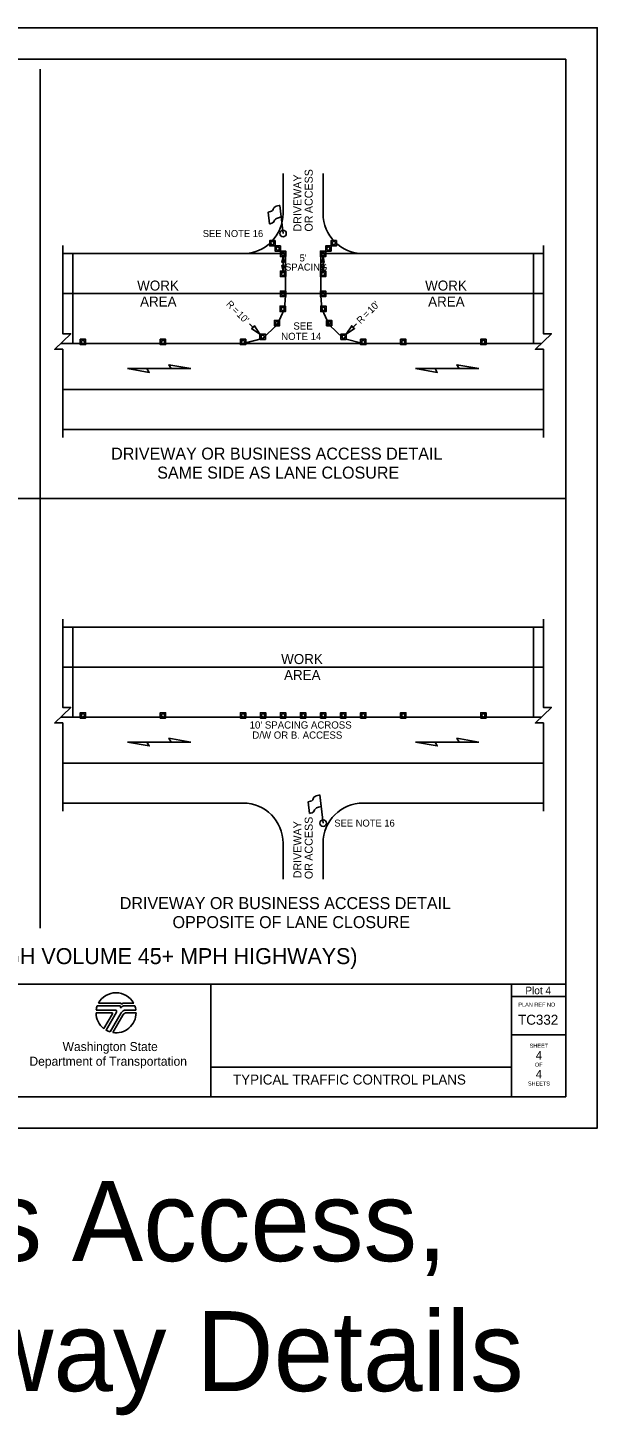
# Model space of a CAD drawing. Extents: x 99999.1 to 100095.7, y 99995 to 100010.7.
# Drawn here: x 100070.38 to 100076.06, y 99996.82 to 100010.69 of the extents above; entities that cross this region are included whole.
import ezdxf

# ---------------------------------------------------------------- set-up
doc = ezdxf.new("R2010")
doc.units = 0
for name, color, linetype in [('RD_ED_DrivewayEdge', 7, 'Continuous'), ('RD_ED_ShoulderPavedEdge', 7, 'Continuous'), ('RD_MK_LineEdgeWhite', 7, 'Continuous'), ('RD_MK_LineSkipCenter', 7, 'Continuous'), ('SH_DE_DetailHeading1Text', 7, 'Continuous'), ('SH_DE_DetailHeading2Text', 7, 'Continuous'), ('SH_GI_PlotLimits', 7, 'Continuous'), ('SH_GI_SheetBorder', 7, 'Continuous'), ('SH_GI_SheetLocationText', 7, 'Continuous'), ('SH_GI_SheetTextInCells', 7, 'Continuous'), ('SH_GI_TitleBlockText', 7, 'Continuous'), ('SH_GI_WSDOTLogo', 7, 'Continuous'), ('TR_WZ_FlaggingStation', 7, 'Continuous'), ('TR_WZ_TrafficCone', 7, 'Continuous'), ('TR_WZ_WorkAreaLabel', 7, 'Continuous'), ('TR_WZ_WorkZoneDetails', 7, 'Continuous'), ('TR_WZ_WorkZoneTextCurrent', 7, 'Continuous')]:
    doc.layers.add(name, color=color, linetype=linetype)

msp = doc.modelspace()

# ---------------------------------------------------------------- linework, layer by layer
at = {"layer": 'RD_ED_DrivewayEdge'}
for p, q in [((100072.925, 100008.83), (100072.925, 100009.23)), ((100073.325, 100008.83), (100073.325, 100009.23)), ((100072.925, 100002.536), (100072.925, 100002.176)), ((100073.325, 100002.536), (100073.325, 100002.176))]:
    msp.add_line(p, q, dxfattribs=at)
for centre, start, end in [((100072.525, 100008.83), 270, 0), ((100073.725, 100008.83), 180, 270), ((100072.525, 100002.536), 0, 90), ((100073.725, 100002.536), 90, 180)]:
    msp.add_arc(centre, 0.4, start, end, dxfattribs=at)
at = {"layer": 'RD_ED_ShoulderPavedEdge'}
for p, q in [((100070.725, 100008.43), (100072.525, 100008.43)), ((100073.725, 100008.43), (100075.525, 100008.43)), ((100070.725, 100006.67), (100075.525, 100006.67)), ((100070.725, 100004.696), (100075.525, 100004.696)), ((100070.725, 100002.936), (100072.525, 100002.936)), ((100073.725, 100002.936), (100075.525, 100002.936))]:
    msp.add_line(p, q, dxfattribs=at)
at = {"layer": 'RD_MK_LineEdgeWhite'}
for p, q in [((100070.725, 100008.03), (100075.525, 100008.03)), ((100070.725, 100007.07), (100075.525, 100007.07)), ((100070.725, 100004.296), (100075.525, 100004.296)), ((100070.725, 100003.336), (100075.525, 100003.336))]:
    msp.add_line(p, q, dxfattribs=at)
at = {"layer": 'RD_MK_LineSkipCenter'}
for points in [[(100075.504, 100007.53), (100070.704, 100007.53)], [(100075.504, 100003.796), (100070.704, 100003.796)]]:
    msp.add_lwpolyline(points, dxfattribs=at)
at = {"layer": 'SH_GI_PlotLimits'}
msp.add_lwpolyline([(100059.062, 99999.687), (100076.062, 99999.687), (100076.062, 100010.687), (100059.062, 100010.687)], close=True, dxfattribs=at)
at = {"layer": 'SH_GI_SheetBorder'}
for p, q in [((100060, 100010.375), (100075.75, 100010.375)), ((100075.75, 100010.375), (100075.75, 100000)), ((100060, 100001.126), (100075.75, 100001.126)), ((100072.205, 100001.126), (100072.205, 100000)), ((100075.208, 100001.126), (100075.208, 100000)), ((100075.208, 100001.001), (100075.75, 100001.001)), ((100075.208, 100000.618), (100075.75, 100000.618)), ((100072.205, 100000.295), (100075.208, 100000.295)), ((100060, 100000), (100075.75, 100000))]:
    msp.add_line(p, q, dxfattribs=at)
at = {"layer": 'SH_GI_WSDOTLogo'}
for p, q in [((100071.059, 100000.866), (100071.25, 100000.866)), ((100071.289, 100000.909), (100071.07, 100000.909)), ((100071.303, 100000.935), (100071.081, 100000.935)), ((100071.433, 100000.935), (100071.335, 100000.935)), ((100071.445, 100000.909), (100071.343, 100000.909)), ((100071.343, 100000.909), (100071.343, 100000.909)), ((100071.356, 100000.866), (100071.456, 100000.866)), ((100071.057, 100000.84), (100071.215, 100000.84)), ((100071.222, 100000.828), (100071.136, 100000.681)), ((100071.261, 100000.846), (100071.157, 100000.667)), ((100071.199, 100000.649), (100071.309, 100000.839)), ((100071.224, 100000.643), (100071.324, 100000.816)), ((100071.365, 100000.839), (100071.457, 100000.839))]:
    msp.add_line(p, q, dxfattribs=at)
for centre, radius, start, end in [((100071.257, 100000.84), 0.2, 28.4787, 151.532), ((100071.257, 100000.84), 0.2, 159.696, 172.5057), ((100071.25, 100000.853), 0.0131, 329.7683, 90), ((100071.289, 100000.895), 0.0148, 327.8418, 89.9985), ((100071.343, 100000.861), 0.0484, 89.9953, 147.8238), ((100071.303, 100000.926), 0.00903, 329.8742, 90.0033), ((100071.356, 100000.812), 0.0542, 90, 149.9974), ((100071.335, 100000.907), 0.0287, 90.0072, 148.1676), ((100071.257, 100000.84), 0.2, 7.4943, 20.2941), ((100071.257, 100000.84), 0.2, 179.9986, 232.8433), ((100071.215, 100000.832), 0.0082, 329.7436, 90), ((100071.257, 100000.84), 0.2, 260.5455, 359.8086), ((100071.365, 100000.792), 0.0476, 90, 150.0543), ((100071.257, 100000.84), 0.2, 239.7929, 253.0448)]:
    msp.add_arc(centre, radius, start, end, dxfattribs=at)
at = {"layer": 'TR_WZ_FlaggingStation'}
for p, q in [((100072.906, 100008.797), (100072.893, 100008.912)), ((100072.925, 100008.63), (100072.893, 100008.911)), ((100072.775, 100008.844), (100072.788, 100008.727)), ((100072.906, 100008.797), (100072.906, 100008.797)), ((100073.175, 100002.949), (100073.188, 100002.832)), ((100073.325, 100002.736), (100073.293, 100003.017)), ((100073.306, 100002.903), (100073.293, 100003.017)), ((100073.306, 100002.903), (100073.306, 100002.903))]:
    msp.add_line(p, q, dxfattribs=at)
for points in [[(100072.893, 100008.912), (100072.887, 100008.91), (100072.869, 100008.907), (100072.856, 100008.903), (100072.846, 100008.897), (100072.837, 100008.892), (100072.832, 100008.885), (100072.827, 100008.877), (100072.827, 100008.871), (100072.821, 100008.862), (100072.811, 100008.854), (100072.798, 100008.849), (100072.775, 100008.844)], [(100072.788, 100008.727), (100072.796, 100008.728), (100072.814, 100008.733), (100072.83, 100008.743), (100072.836, 100008.754), (100072.84, 100008.764), (100072.849, 100008.775), (100072.86, 100008.781), (100072.878, 100008.788), (100072.906, 100008.797)], [(100073.293, 100003.017), (100073.287, 100003.016), (100073.269, 100003.012), (100073.256, 100003.008), (100073.246, 100003.002), (100073.237, 100002.997), (100073.232, 100002.991), (100073.227, 100002.983), (100073.227, 100002.977), (100073.221, 100002.967), (100073.211, 100002.96), (100073.198, 100002.955), (100073.175, 100002.949)], [(100073.188, 100002.832), (100073.196, 100002.834), (100073.214, 100002.838), (100073.23, 100002.849), (100073.236, 100002.859), (100073.24, 100002.87), (100073.249, 100002.88), (100073.26, 100002.887), (100073.278, 100002.894), (100073.306, 100002.903)]]:
    msp.add_lwpolyline(points, dxfattribs=at)
for centre in [(100072.925, 100008.63), (100073.325, 100002.736)]:
    msp.add_circle(centre, 0.0325, dxfattribs=at)
at = {"layer": 'TR_WZ_TrafficCone'}
for points in [[(100072.845, 100008.56), (100072.845, 100008.507), (100072.792, 100008.507), (100072.792, 100008.56), (100072.845, 100008.56)], [(100072.792, 100008.56), (100072.792, 100008.507), (100072.845, 100008.507), (100072.845, 100008.56), (100072.792, 100008.56)], [(100072.898, 100008.507), (100072.898, 100008.454), (100072.845, 100008.454), (100072.845, 100008.507), (100072.898, 100008.507)], [(100072.845, 100008.507), (100072.845, 100008.454), (100072.898, 100008.454), (100072.898, 100008.507), (100072.845, 100008.507)], [(100073.352, 100008.507), (100073.352, 100008.454), (100073.405, 100008.454), (100073.405, 100008.507), (100073.352, 100008.507)], [(100073.405, 100008.507), (100073.405, 100008.454), (100073.352, 100008.454), (100073.352, 100008.507), (100073.405, 100008.507)], [(100073.405, 100008.56), (100073.405, 100008.507), (100073.458, 100008.507), (100073.458, 100008.56), (100073.405, 100008.56)], [(100073.458, 100008.56), (100073.458, 100008.507), (100073.405, 100008.507), (100073.405, 100008.56), (100073.458, 100008.56)], [(100072.898, 100008.454), (100072.952, 100008.454), (100072.952, 100008.4), (100072.898, 100008.4), (100072.898, 100008.454)], [(100072.898, 100008.4), (100072.952, 100008.4), (100072.952, 100008.454), (100072.898, 100008.454), (100072.898, 100008.4)], [(100073.352, 100008.454), (100073.298, 100008.454), (100073.298, 100008.4), (100073.352, 100008.4), (100073.352, 100008.454)], [(100073.352, 100008.4), (100073.298, 100008.4), (100073.298, 100008.454), (100073.352, 100008.454), (100073.352, 100008.4)], [(100072.898, 100008.254), (100072.952, 100008.254), (100072.952, 100008.2), (100072.898, 100008.2), (100072.898, 100008.254)], [(100072.898, 100008.2), (100072.952, 100008.2), (100072.952, 100008.254), (100072.898, 100008.254), (100072.898, 100008.2)], [(100073.352, 100008.254), (100073.298, 100008.254), (100073.298, 100008.2), (100073.352, 100008.2), (100073.352, 100008.254)], [(100073.352, 100008.2), (100073.298, 100008.2), (100073.298, 100008.254), (100073.352, 100008.254), (100073.352, 100008.2)], [(100072.898, 100008.054), (100072.952, 100008.054), (100072.952, 100008), (100072.898, 100008), (100072.898, 100008.054)], [(100072.898, 100008), (100072.952, 100008), (100072.952, 100008.054), (100072.898, 100008.054), (100072.898, 100008)], [(100073.352, 100008.054), (100073.298, 100008.054), (100073.298, 100008), (100073.352, 100008), (100073.352, 100008.054)], [(100073.352, 100008), (100073.298, 100008), (100073.298, 100008.054), (100073.352, 100008.054), (100073.352, 100008)], [(100072.896, 100007.904), (100072.949, 100007.904), (100072.949, 100007.85), (100072.896, 100007.85), (100072.896, 100007.904)], [(100072.896, 100007.85), (100072.949, 100007.85), (100072.949, 100007.904), (100072.896, 100007.904), (100072.896, 100007.85)], [(100073.354, 100007.904), (100073.301, 100007.904), (100073.301, 100007.85), (100073.354, 100007.85), (100073.354, 100007.904)], [(100073.354, 100007.85), (100073.301, 100007.85), (100073.301, 100007.904), (100073.354, 100007.904), (100073.354, 100007.85)], [(100072.838, 100007.762), (100072.891, 100007.762), (100072.891, 100007.708), (100072.838, 100007.708), (100072.838, 100007.762)], [(100072.838, 100007.708), (100072.891, 100007.708), (100072.891, 100007.762), (100072.838, 100007.762), (100072.838, 100007.708)], [(100073.412, 100007.762), (100073.359, 100007.762), (100073.359, 100007.708), (100073.412, 100007.708), (100073.412, 100007.762)], [(100073.412, 100007.708), (100073.359, 100007.708), (100073.359, 100007.762), (100073.412, 100007.762), (100073.412, 100007.708)], [(100070.899, 100007.574), (100070.952, 100007.574), (100070.952, 100007.52), (100070.899, 100007.52), (100070.899, 100007.574)], [(100070.899, 100007.52), (100070.952, 100007.52), (100070.952, 100007.574), (100070.899, 100007.574), (100070.899, 100007.52)], [(100071.699, 100007.574), (100071.752, 100007.574), (100071.752, 100007.52), (100071.699, 100007.52), (100071.699, 100007.574)], [(100071.699, 100007.52), (100071.752, 100007.52), (100071.752, 100007.574), (100071.699, 100007.574), (100071.699, 100007.52)], [(100072.499, 100007.574), (100072.552, 100007.574), (100072.552, 100007.52), (100072.499, 100007.52), (100072.499, 100007.574)], [(100072.499, 100007.52), (100072.552, 100007.52), (100072.552, 100007.574), (100072.499, 100007.574), (100072.499, 100007.52)], [(100072.694, 100007.625), (100072.748, 100007.625), (100072.748, 100007.571), (100072.694, 100007.571), (100072.694, 100007.625)], [(100072.694, 100007.571), (100072.748, 100007.571), (100072.748, 100007.625), (100072.694, 100007.625), (100072.694, 100007.571)], [(100073.556, 100007.625), (100073.502, 100007.625), (100073.502, 100007.571), (100073.556, 100007.571), (100073.556, 100007.625)], [(100073.556, 100007.571), (100073.502, 100007.571), (100073.502, 100007.625), (100073.556, 100007.625), (100073.556, 100007.571)], [(100073.699, 100007.574), (100073.752, 100007.574), (100073.752, 100007.52), (100073.699, 100007.52), (100073.699, 100007.574)], [(100073.699, 100007.52), (100073.752, 100007.52), (100073.752, 100007.574), (100073.699, 100007.574), (100073.699, 100007.52)], [(100074.099, 100007.574), (100074.152, 100007.574), (100074.152, 100007.52), (100074.099, 100007.52), (100074.099, 100007.574)], [(100074.099, 100007.52), (100074.152, 100007.52), (100074.152, 100007.574), (100074.099, 100007.574), (100074.099, 100007.52)], [(100074.899, 100007.574), (100074.952, 100007.574), (100074.952, 100007.52), (100074.899, 100007.52), (100074.899, 100007.574)], [(100074.899, 100007.52), (100074.952, 100007.52), (100074.952, 100007.574), (100074.899, 100007.574), (100074.899, 100007.52)], [(100070.899, 100003.839), (100070.952, 100003.839), (100070.952, 100003.786), (100070.899, 100003.786), (100070.899, 100003.839)], [(100070.899, 100003.786), (100070.952, 100003.786), (100070.952, 100003.839), (100070.899, 100003.839), (100070.899, 100003.786)], [(100071.699, 100003.839), (100071.752, 100003.839), (100071.752, 100003.786), (100071.699, 100003.786), (100071.699, 100003.839)], [(100071.699, 100003.786), (100071.752, 100003.786), (100071.752, 100003.839), (100071.699, 100003.839), (100071.699, 100003.786)], [(100072.499, 100003.839), (100072.552, 100003.839), (100072.552, 100003.786), (100072.499, 100003.786), (100072.499, 100003.839)], [(100072.499, 100003.786), (100072.552, 100003.786), (100072.552, 100003.839), (100072.499, 100003.839), (100072.499, 100003.786)], [(100072.699, 100003.839), (100072.752, 100003.839), (100072.752, 100003.786), (100072.699, 100003.786), (100072.699, 100003.839)], [(100072.699, 100003.786), (100072.752, 100003.786), (100072.752, 100003.839), (100072.699, 100003.839), (100072.699, 100003.786)], [(100072.899, 100003.839), (100072.952, 100003.839), (100072.952, 100003.786), (100072.899, 100003.786), (100072.899, 100003.839)], [(100072.899, 100003.786), (100072.952, 100003.786), (100072.952, 100003.839), (100072.899, 100003.839), (100072.899, 100003.786)], [(100073.099, 100003.839), (100073.152, 100003.839), (100073.152, 100003.786), (100073.099, 100003.786), (100073.099, 100003.839)], [(100073.099, 100003.786), (100073.152, 100003.786), (100073.152, 100003.839), (100073.099, 100003.839), (100073.099, 100003.786)], [(100073.299, 100003.839), (100073.352, 100003.839), (100073.352, 100003.786), (100073.299, 100003.786), (100073.299, 100003.839)], [(100073.299, 100003.786), (100073.352, 100003.786), (100073.352, 100003.839), (100073.299, 100003.839), (100073.299, 100003.786)], [(100073.499, 100003.839), (100073.552, 100003.839), (100073.552, 100003.786), (100073.499, 100003.786), (100073.499, 100003.839)], [(100073.499, 100003.786), (100073.552, 100003.786), (100073.552, 100003.839), (100073.499, 100003.839), (100073.499, 100003.786)], [(100073.699, 100003.839), (100073.752, 100003.839), (100073.752, 100003.786), (100073.699, 100003.786), (100073.699, 100003.839)], [(100073.699, 100003.786), (100073.752, 100003.786), (100073.752, 100003.839), (100073.699, 100003.839), (100073.699, 100003.786)], [(100074.099, 100003.839), (100074.152, 100003.839), (100074.152, 100003.786), (100074.099, 100003.786), (100074.099, 100003.839)], [(100074.099, 100003.786), (100074.152, 100003.786), (100074.152, 100003.839), (100074.099, 100003.839), (100074.099, 100003.786)], [(100074.899, 100003.839), (100074.952, 100003.839), (100074.952, 100003.786), (100074.899, 100003.786), (100074.899, 100003.839)], [(100074.899, 100003.786), (100074.952, 100003.786), (100074.952, 100003.839), (100074.899, 100003.839), (100074.899, 100003.786)]]:
    msp.add_lwpolyline(points, dxfattribs=at)
for centre in [(100072.818, 100008.534), (100072.872, 100008.48), (100073.378, 100008.48), (100073.432, 100008.534), (100072.925, 100008.427), (100073.325, 100008.427), (100072.925, 100008.227), (100073.325, 100008.227), (100072.925, 100008.027), (100073.325, 100008.027), (100072.922, 100007.877), (100073.328, 100007.877), (100072.865, 100007.735), (100073.385, 100007.735), (100070.926, 100007.547), (100071.726, 100007.547), (100072.526, 100007.547), (100072.721, 100007.598), (100073.529, 100007.598), (100073.726, 100007.547), (100074.126, 100007.547), (100074.926, 100007.547), (100070.926, 100003.813), (100071.726, 100003.813), (100072.526, 100003.813), (100072.726, 100003.813), (100072.926, 100003.813), (100073.126, 100003.813), (100073.326, 100003.813), (100073.526, 100003.813), (100073.726, 100003.813), (100074.126, 100003.813), (100074.926, 100003.813)]:
    msp.add_circle(centre, 0.0167, dxfattribs=at)
at = {"layer": 'TR_WZ_WorkZoneDetails'}
for p, q in [((100070.5, 100010.275), (100070.5, 100001.686)), ((100072.925, 100008.346), (100072.925, 100008.308)), ((100073.325, 100008.346), (100073.325, 100008.308)), ((100072.628, 100007.691), (100072.59, 100007.729)), ((100073.622, 100007.691), (100073.66, 100007.729)), ((100071.566, 100007.28), (100071.808, 100007.28)), ((100071.808, 100007.28), (100071.566, 100007.28)), ((100074.443, 100007.28), (100074.684, 100007.28)), ((100074.684, 100007.28), (100074.443, 100007.28)), ((100070.5, 100005.98), (100065.25, 100005.98)), ((100075.75, 100005.98), (100070.5, 100005.98)), ((100071.566, 100003.546), (100071.808, 100003.546)), ((100071.808, 100003.546), (100071.566, 100003.546)), ((100074.443, 100003.546), (100074.684, 100003.546)), ((100074.684, 100003.546), (100074.443, 100003.546))]:
    msp.add_line(p, q, dxfattribs=at)
for points in [[(100070.725, 100006.59), (100070.725, 100007.473), (100070.645, 100007.473), (100070.805, 100007.628), (100070.725, 100007.628), (100070.725, 100008.51)], [(100075.525, 100006.59), (100075.525, 100007.473), (100075.445, 100007.473), (100075.605, 100007.628), (100075.525, 100007.628), (100075.525, 100008.51)], [(100070.725, 100002.856), (100070.725, 100003.738), (100070.645, 100003.738), (100070.805, 100003.893), (100070.725, 100003.893), (100070.725, 100004.776)], [(100075.525, 100002.856), (100075.525, 100003.738), (100075.445, 100003.738), (100075.605, 100003.893), (100075.525, 100003.893), (100075.525, 100004.776)]]:
    msp.add_lwpolyline(points, dxfattribs=at)
for points in [[(100072.948, 100008.43), (100072.948, 100008.207), (100072.948, 100008.007), (100072.939, 100007.877), (100072.939, 100007.877), (100072.939, 100007.877), (100072.865, 100007.718), (100072.865, 100007.718), (100072.865, 100007.718), (100072.721, 100007.581), (100072.526, 100007.53), (100071.529, 100007.53), (100070.949, 100007.53), (100070.825, 100007.53), (100070.825, 100008.43)], [(100072.925, 100008.4), (100072.936, 100008.343), (100072.925, 100008.346), (100072.914, 100008.343)], [(100075.425, 100008.43), (100075.425, 100008.03), (100075.425, 100007.53), (100074.501, 100007.53), (100074.501, 100007.53), (100074.501, 100007.53), (100073.726, 100007.53), (100073.726, 100007.53), (100073.726, 100007.53), (100073.529, 100007.581), (100073.385, 100007.718), (100073.311, 100007.877), (100073.302, 100008.007), (100073.302, 100008.207), (100073.302, 100008.43)], [(100073.325, 100008.4), (100073.336, 100008.343), (100073.325, 100008.346), (100073.314, 100008.343)], [(100072.925, 100008.254), (100072.936, 100008.311), (100072.925, 100008.308), (100072.914, 100008.311)], [(100073.325, 100008.254), (100073.336, 100008.311), (100073.325, 100008.308), (100073.314, 100008.311)], [(100072.694, 100007.625), (100072.611, 100007.681), (100072.628, 100007.691), (100072.639, 100007.708)], [(100073.556, 100007.625), (100073.639, 100007.681), (100073.622, 100007.691), (100073.611, 100007.708)], [(100071.37, 100007.28), (100071.589, 100007.242), (100071.566, 100007.28)], [(100072.004, 100007.28), (100071.785, 100007.319), (100071.808, 100007.28)], [(100074.247, 100007.28), (100074.465, 100007.242), (100074.443, 100007.28)], [(100074.881, 100007.28), (100074.662, 100007.319), (100074.684, 100007.28)], [(100070.825, 100004.696), (100070.825, 100003.796), (100075.425, 100003.796), (100075.425, 100004.696)], [(100071.37, 100003.546), (100071.589, 100003.507), (100071.566, 100003.546)], [(100072.004, 100003.546), (100071.785, 100003.584), (100071.808, 100003.546)], [(100074.247, 100003.546), (100074.465, 100003.507), (100074.443, 100003.546)], [(100074.881, 100003.546), (100074.662, 100003.584), (100074.684, 100003.546)]]:
    msp.add_lwpolyline(points, close=True, dxfattribs=at)

# ---------------------------------------------------------------- texts
at = {"layer": 'SH_DE_DetailHeading1Text'}
msp.add_text('ALTERNATING 1-LANE, 2-WAY TRAFFIC: AFAD-CONTROLLED + TEMP. RUMBLE STRIPS (HIGH VOLUME 45+ MPH HIGHWAYS)', height=0.16, rotation=360, dxfattribs=at).set_placement((100060.817, 100001.326))
at = {"layer": 'SH_DE_DetailHeading2Text'}
for s, p in [('DRIVEWAY OR BUSINESS ACCESS DETAIL', (100071.208, 100006.37)), ('SAME SIDE AS LANE CLOSURE', (100071.668, 100006.18)), ('DRIVEWAY OR BUSINESS ACCESS DETAIL', (100071.294, 100001.876)), ('OPPOSITE OF LANE CLOSURE', (100071.821, 100001.686))]:
    msp.add_text(s, height=0.12, rotation=360, dxfattribs=at).set_placement(p)
at = {"layer": 'SH_GI_SheetBorder'}
msp.add_text('PLAN REF NO', height=0.04003, dxfattribs=at).set_placement((100075.275, 100000.901))
at = {"layer": 'SH_GI_SheetLocationText'}
for s, height, p in [('Plot 4', 0.075, (100075.345, 100001.025)), ('Driveway, Business Access,', 0.8, (100061.184, 99998.357)), ('or Intersecting Roadway Details', 0.8, (100060.225, 99997.057))]:
    msp.add_text(s, height=height, dxfattribs=at).set_placement(p)
at = {"layer": 'SH_GI_SheetTextInCells'}
for s, height, p in [('Washington State', 0.09007, (100070.723, 100000.457)), ('SHEET', 0.04, (100075.388, 100000.49)), ('Department of Transportation', 0.09007, (100070.392, 100000.31)), ('OF', 0.04, (100075.441, 100000.301)), ('SHEETS', 0.04, (100075.37, 100000.112))]:
    msp.add_text(s, height=height, dxfattribs=at).set_placement(p)
at = {"layer": 'SH_GI_TitleBlockText'}
for s, height, p in [('TC332', 0.1, (100075.272, 100000.72)), ('4', 0.085, (100075.449, 100000.372)), ('TYPICAL TRAFFIC CONTROL PLANS', 0.1, (100072.425, 100000.122)), ('4', 0.085, (100075.449, 100000.184))]:
    msp.add_text(s, height=height, dxfattribs=at).set_placement(p)
at = {"layer": 'TR_WZ_WorkAreaLabel'}
for s, p in [('WORK', (100071.468, 100008.06)), ('WORK', (100074.344, 100008.06)), ('AREA', (100071.497, 100007.9)), ('AREA', (100074.374, 100007.9)), ('WORK', (100072.906, 100004.326)), ('AREA', (100072.935, 100004.166))]:
    msp.add_text(s, height=0.1, dxfattribs=at).set_placement(p)
at = {"layer": 'TR_WZ_WorkZoneTextCurrent'}
for s, height, rotation, p in [('DRIVEWAY', 0.08, 90, (100073.109, 100008.65)), ('ACCESS', 0.08, 90, (100073.221, 100008.834)), ('OR', 0.08, 90, (100073.221, 100008.65)), ('R', 0.07, 315, (100072.351, 100007.919)), ("10'", 0.07, 45, (100073.808, 100007.827)), ('=', 0.07, 315, (100072.41, 100007.859)), ("10'", 0.07, 315, (100072.457, 100007.813)), ('R', 0.07, 45, (100073.701, 100007.721)), ('=', 0.07, 45, (100073.761, 100007.78)), ('ACCESS', 0.08, 90, (100073.221, 100002.36)), ('DRIVEWAY', 0.08, 90, (100073.109, 100002.184)), ('OR', 0.08, 90, (100073.221, 100002.176))]:
    msp.add_text(s, height=height, rotation=rotation, dxfattribs=at).set_placement(p)
for s, height, p in [('SEE NOTE 16', 0.07, (100072.123, 100008.595)), ("5'", 0.07, (100073.09, 100008.351)), ('SPACING', 0.07, (100072.945, 100008.26)), ('SEE', 0.072, (100073.028, 100007.67)), ('NOTE 14', 0.072, (100072.906, 100007.566)), ("10' SPACING ACROSS", 0.072, (100072.591, 100003.681)), ('D/W OR B. ACCESS', 0.072, (100072.618, 100003.58)), ('SEE NOTE 16', 0.07, (100073.437, 100002.701))]:
    msp.add_text(s, height=height, dxfattribs=at).set_placement(p)

doc.saveas('drawing.dxf')
